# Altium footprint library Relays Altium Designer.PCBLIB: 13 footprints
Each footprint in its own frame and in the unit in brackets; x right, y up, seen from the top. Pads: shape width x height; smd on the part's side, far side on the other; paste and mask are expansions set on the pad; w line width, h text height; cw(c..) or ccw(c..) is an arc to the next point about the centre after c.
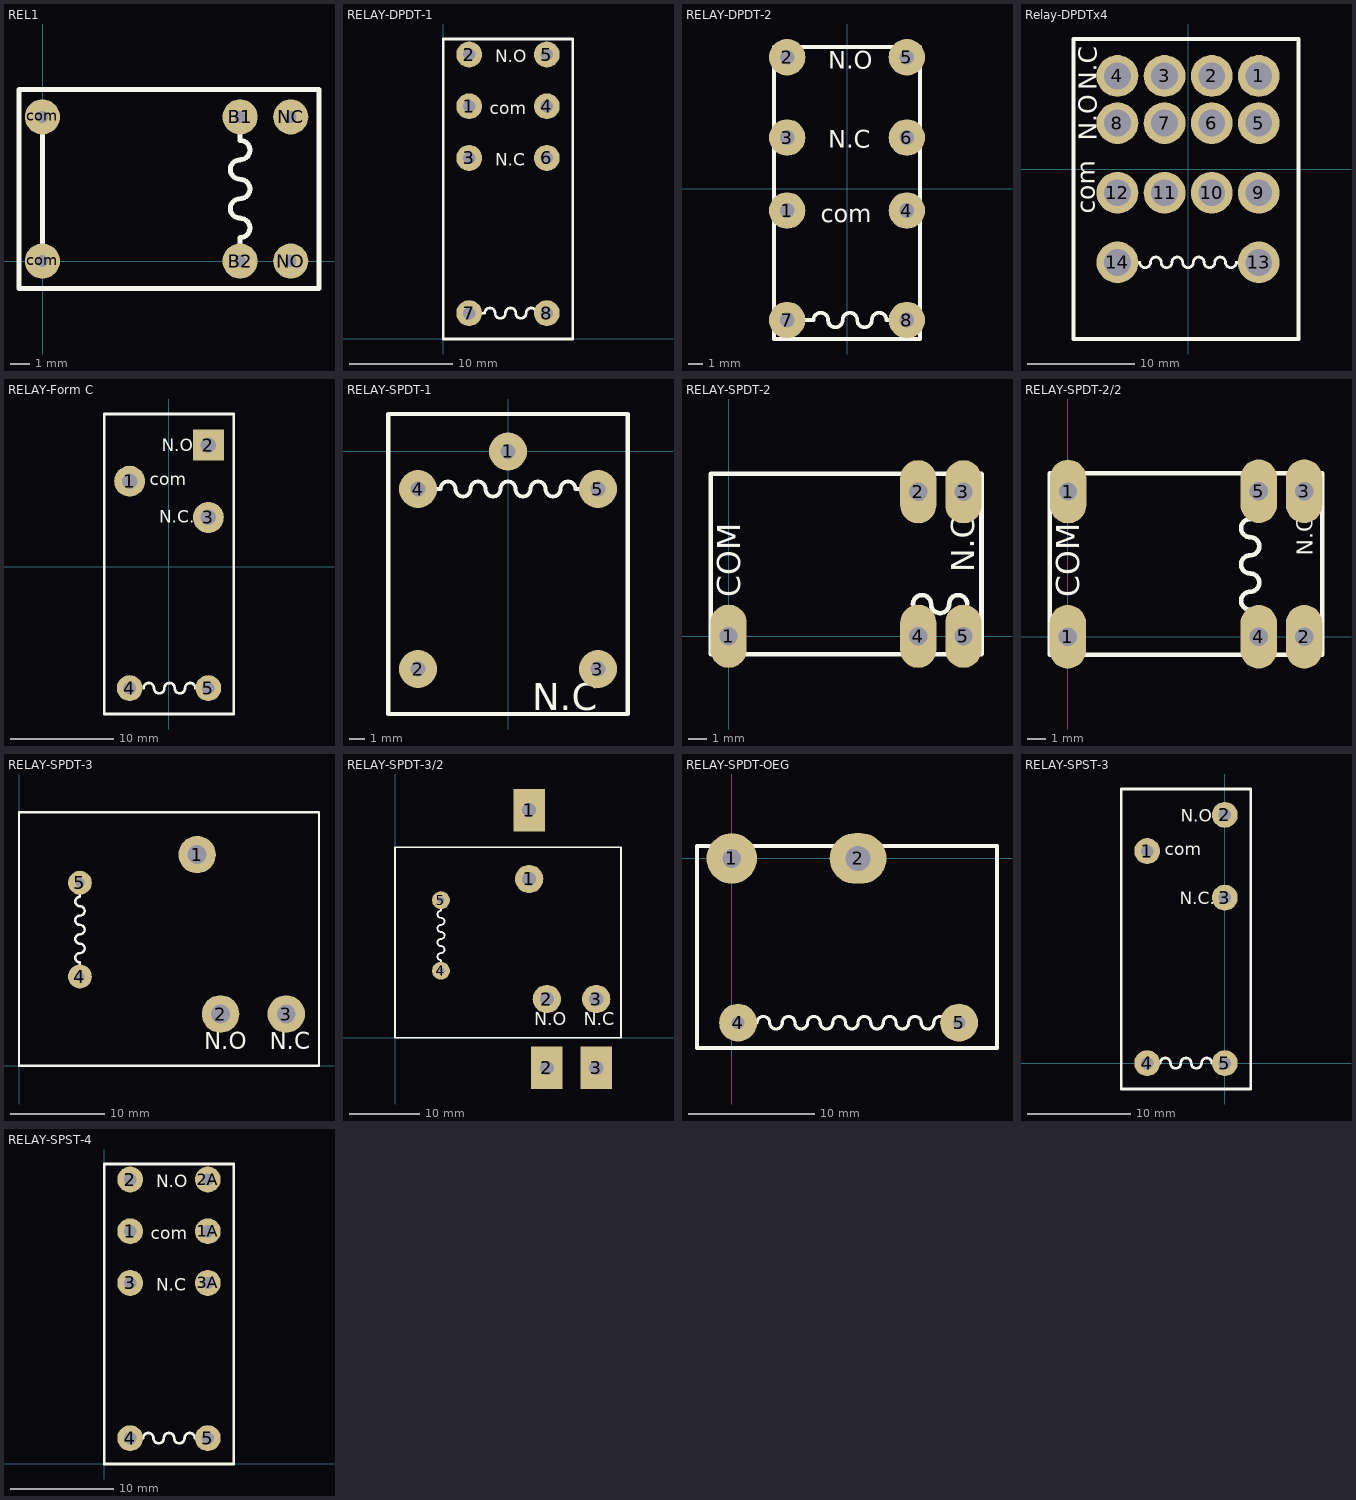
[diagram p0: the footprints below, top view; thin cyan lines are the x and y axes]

## REL1 [mm] "altium designer (M.Hariri)"
pads (6):
  round 1.8 hole 0.6: B1(10.141,7.409) B2(10.141,0.009) com(-0.009,0.009) com(-0.009,7.409) NC(12.741,7.409) NO(12.741,0.009)
Top Overlay:
  lines w0.254: -0.009,0.009 -0.009,7.409 ; 10.141,0.009 10.141,1.209 ccw(c10.141,1.709) 10.141,2.209 cw(c10.141,2.709) 10.141,3.209 ccw(c10.141,3.709) 10.141,4.209 cw(c10.141,4.709) 10.141,5.209 ccw(c10.141,5.709) 10.141,6.209 10.141,7.409 ; -1.209,-1.391 -1.209,8.809 14.191,8.809 14.191,-1.391 -1.209,-1.391

## RELAY-DPDT-1 [mm] "altium designer (M.Hariri)"
pads (8):
  round 2.5 hole 1.2: 1(2.5,22.5) 2(2.5,27.5) 3(2.5,17.5) 4(10,22.5) 5(10,27.5) 6(10,17.5) 7(2.5,2.5) 8(10,2.5)
Top Overlay:
  lines w0.254: 2.8,2.5 4,2.5 cw(c4.5,2.5) 5,2.5 ccw(c5.5,2.5) 6,2.5 cw(c6.5,2.5) 7,2.5 ccw(c7.5,2.5) 8,2.5 cw(c8.5,2.5) 9,2.5 9.75,2.5 ; 0,0 0,29 12.5,29 12.5,0 0,0
  text "N.O" at 5,26.75 h1.2
  text "com" at 4.5,21.75 h1.2
  text "N.C" at 5,16.75 h1.2

## RELAY-DPDT-2 [mm] "altium designer (M.Hariri)"
height 11
pads (8):
  round 2.5 hole 1: 1(-4.1,-1.5) 2(-4.1,9) 3(-4.1,3.5) 4(4.1,-1.5) 5(4.1,9) 6(4.1,3.5) 7(-4.1,-9) 8(4.1,-9)
Top Overlay:
  lines w0.254: -3.5,-9 -2.3,-9 cw(c-1.8,-9) -1.3,-9 ccw(c-0.8,-9) -0.3,-9 cw(c0.2,-9) 0.7,-9 ccw(c1.2,-9) 1.7,-9 cw(c2.2,-9) 2.7,-9 3.45,-9 ; -5,-10.3 5,-10.3 5,9.7 -5,9.7 -5,-10.3
  text "N.C" at -1.3,2.8 h1.2
  text "com" at -1.8,-2.3 h1.2
  text "N.O" at -1.3,8.2 h1.2

## Relay-DPDTx4 [mm] "altium designer (M.Hariri)"
pads (14):
  round 3.9 hole 2.5: 1(6.6,8.7) 2(2.2,8.7) 3(-2.2,8.7) 4(-6.6,8.7) 5(6.6,4.3) 6(2.2,4.3) 7(-2.2,4.3) 8(-6.6,4.3) 9(6.6,-2.2) 10(2.2,-2.2) 11(-2.2,-2.2) 12(-6.6,-2.2) 13(6.6,-8.7) 14(-6.6,-8.7)
Top Overlay:
  lines w0.254: -5.262,-8.701 -4.512,-8.701 ccw(c-4.012,-8.701) -3.512,-8.701 cw(c-3.012,-8.701) -2.512,-8.701 ccw(c-2.012,-8.701) -1.512,-8.701 cw(c-1.012,-8.701) -0.512,-8.701 ccw(c-0.012,-8.701) 0.488,-8.701 cw(c0.988,-8.701) 1.488,-8.701 ccw(c1.988,-8.701) 2.488,-8.701 cw(c2.988,-8.701) 3.488,-8.701 ccw(c3.988,-8.701) 4.488,-8.701 5.238,-8.701
  lines w0.4: -10.7,-15.85 -10.7,12.15 10.3,12.15 10.3,-15.85 -10.7,-15.85
  text "N.C" at -8.51,7.35 h1.7
  text "N.O" at -8.51,2.65 h1.7
  text "com" at -8.71,-4.15 h1.7

## RELAY-Form C [mm] "altium designer (M.Hariri)"
height 25
pads (5):
  round 3 hole 1.5: 1(-3.8,8.25) 3(3.8,4.75)
  rect 3x3 hole 1.5: 2(3.8,11.75)
  round 2.5 hole 1.2: 4(-3.8,-11.75) 5(3.8,-11.75)
Top Overlay:
  lines w0.254: -2.45,-11.75 cw(c-1.95,-11.75) -1.45,-11.75 ccw(c-0.95,-11.75) -0.45,-11.75 cw(c0.05,-11.75) 0.55,-11.75 ccw(c1.05,-11.75) 1.55,-11.75 cw(c2.05,-11.75) 2.55,-11.75 ; -6.25,-14.25 6.25,-14.25 6.25,14.75 -6.25,14.75 -6.25,-14.25
  text "N.C." at -0.95,4.25 h1.2
  text "com" at -1.85,7.85 h1.2
  text "N.O." at -0.7,11.15 h1.2

## RELAY-SPDT-1 [mm] "altium designer (M.Hariri)"
pads (5):
  round 2.54 hole 1: 1(0,0) 2(-6,-14.5) 3(6,-14.5) 4(-6,-2.5) 5(6,-2.5)
Top Overlay:
  lines w0.254: -5.7,-2.5 -4.5,-2.5 cw(c-4,-2.5) -3.5,-2.5 ccw(c-3,-2.5) -2.5,-2.5 cw(c-2,-2.5) -1.5,-2.5 ccw(c-1,-2.5) -0.5,-2.5 cw(c0,-2.5) 0.5,-2.5 ccw(c1,-2.5) 1.5,-2.5 cw(c2,-2.5) 2.5,-2.5 ccw(c3,-2.5) 3.5,-2.5 cw(c4,-2.5) 4.5,-2.5 ; 4.6,-2.5 5.8,-2.5
  lines w0.3: -8,-17.5 -8,2.5 8,2.5 8,-17.5 -8,-17.5
  text "N.C" at 1.62,-17.264 h1.8

## RELAY-SPDT-2 [mm] "altium designer (M.Hariri)"
pads (5):
  oval 2x3.5 hole 1: 1(0,0) 2(10.5,8) 3(13,8) 4(10.5,0) 5(13,0)
Top Overlay:
  lines w0.254: 10.208,1.778 cw(c10.708,1.778) 11.208,1.778 ccw(c11.708,1.778) 12.208,1.778 cw(c12.708,1.778) 13.208,1.778 ; -1,-1 14,-1 14,9 -1,9 -1,-1
  text "COM" at 0.635,2.159 h1.27
  text "N.C" at 13.589,3.556 h1.27

## RELAY-SPDT-2/2 [mm] "altium designer (M.Hariri)"
pads (6):
  oval 2x3.5 hole 1: 1(0,0) 1(0.016,7.984) 2(13,0) 3(13,8) 4(10.5,0) 5(10.5,8)
Top Overlay:
  lines w0.254: 10.033,1.477 cw(c10.033,1.977) 10.033,2.477 ccw(c10.033,2.977) 10.033,3.477 cw(c10.033,3.977) 10.033,4.477 ccw(c10.033,4.977) 10.033,5.477 cw(c10.033,5.977) 10.033,6.477 ; -1,-1 14,-1 14,9 -1,9 -1,-1
  text "COM" at 0.635,2.159 h1.27
  text "N.C" at 13.462,4.445 h0.89

## RELAY-SPDT-3 [mm] "altium designer (M.Hariri)"
pads (5):
  round 4 hole 2: 1(19,22.5) 2(21.5,5.5) 3(28.5,5.5)
  round 2.54 hole 1: 4(6.5,9.5) 5(6.5,19.5)
Top Overlay:
  lines w0.254: 6.5,9.8 6.5,11 cw(c6.5,11.5) 6.5,12 ccw(c6.5,12.5) 6.5,13 cw(c6.5,13.5) 6.5,14 ccw(c6.5,14.5) 6.5,15 cw(c6.5,15.5) 6.5,16 ccw(c6.5,16.5) 6.5,17 cw(c6.5,17.5) 6.5,18 6.5,19.2 ; 0,0 0,27 32,27 32,0 0,0
  text "N.C" at 26.75,1.75 h1.8
  text "N.O" at 19.75,1.75 h1.8

## RELAY-SPDT-3/2 [mm] "altium designer (M.Hariri)"
pads (8):
  round 4 hole 2: 1(19,22.5) 2(21.5,5.5) 3(28.5,5.5)
  rect 4.5x6 hole 2: 1(19,32.25) 2(21.5,-4.25) 3(28.5,-4.25)
  round 2.54 hole 1: 4(6.5,9.5) 5(6.5,19.5)
Top Overlay:
  lines w0.254: 6.5,9.8 6.5,11 cw(c6.5,11.5) 6.5,12 ccw(c6.5,12.5) 6.5,13 cw(c6.5,13.5) 6.5,14 ccw(c6.5,14.5) 6.5,15 cw(c6.5,15.5) 6.5,16 ccw(c6.5,16.5) 6.5,17 cw(c6.5,17.5) 6.5,18 6.5,19.2 ; 0,0 0,27 32,27 32,0 0,0
  text "N.C" at 26.75,1.75 h1.8
  text "N.O" at 19.75,1.75 h1.8

## RELAY-SPDT-OEG [mm] "altium designer (M.Hariri)"
pads (4):
  round 4 hole 1.5: 1(0,0)
  oval 4.5x4 hole 2: 2(10,0)
  round 3 hole 1: 4(0.5,-13) 5(18,-13)
Top Overlay:
  lines w0.254: 0.8,-13 2,-13 cw(c2.5,-13) 3,-13 ccw(c3.5,-13) 4,-13 cw(c4.5,-13) 5,-13 ccw(c5.5,-13) 6,-13 cw(c6.5,-13) 7,-13 ccw(c7.5,-13) 8,-13 cw(c8.5,-13) 9,-13 ccw(c9.5,-13) 10,-13 cw(c10.5,-13) 11,-13 ccw(c11.5,-13) 12,-13 cw(c12.5,-13) 13,-13 ccw(c13.5,-13) 14,-13 cw(c14.5,-13) 15,-13 ccw(c15.5,-13) 16,-13 cw(c16.5,-13) 17,-13 18,-13
  lines w0.305: -2.75,-15 21,-15 21,1 -2.75,1 -2.75,-15

## RELAY-SPST-3 [mm] "altium designer (M.Hariri)"
height 25
pads (5):
  round 2.5 hole 1.2: 1(-7.5,20.5) 2(0,24) 3(0,16) 4(-7.5,0) 5(0,0)
Top Overlay:
  lines w0.254: -6.25,0 cw(c-5.75,0) -5.25,0 ccw(c-4.75,0) -4.25,0 cw(c-3.75,0) -3.25,0 ccw(c-2.75,0) -2.25,0 cw(c-1.75,0) -1.25,0 ; -10,-2.5 -10,26.5 2.5,26.5 2.5,-2.5 -10,-2.5
  text "N.O." at -4.25,23.35 h1.2
  text "com" at -5.8,20.1 h1.2
  text "N.C." at -4.35,15.35 h1.2

## RELAY-SPST-4 [mm] "altium designer (M.Hariri)"
height 25
pads (8):
  round 2.5 hole 1.2: 1(2.5,22.5) 1A(10,22.5) 2(2.5,27.5) 2A(10,27.5) 3(2.5,17.5) 3A(10,17.5) 4(2.5,2.5) 5(10,2.5)
Top Overlay:
  lines w0.254: 3.75,2.5 cw(c4.25,2.5) 4.75,2.5 ccw(c5.25,2.5) 5.75,2.5 cw(c6.25,2.5) 6.75,2.5 ccw(c7.25,2.5) 7.75,2.5 cw(c8.25,2.5) 8.75,2.5 ; 0,0 12.5,0 12.5,29 0,29 0,0
  text "N.C" at 5,16.75 h1.2
  text "com" at 4.5,21.75 h1.2
  text "N.O" at 5,26.75 h1.2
